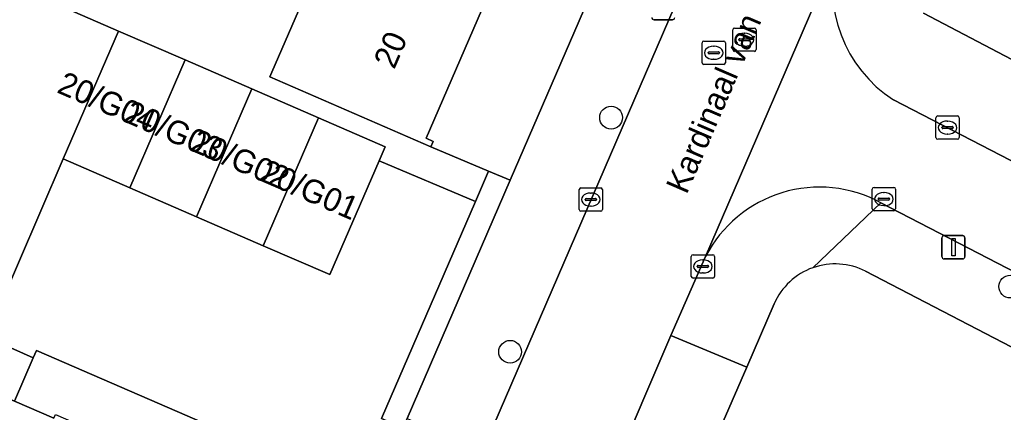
# Model space of a CAD drawing. Extents: x 162803 to 163818, y 381639 to 382475.
# Drawn here: x 163434.73 to 163477.02, y 381838.38 to 381855.24 of the extents above; entities that cross this region are included whole.
import ezdxf

# ---------------------------------------------------------------- set-up
doc = ezdxf.new("R2010")
doc.units = 0
for name, color, linetype in [('IMGEO_Boom', 7, 'Continuous'), ('IMGEO_Erf', 7, 'Continuous'), ('IMGEO_Groenvoorziening', 7, 'Continuous'), ('IMGEO_Kolk', 7, 'Continuous'), ('IMGEO_Lichtmast', 7, 'Continuous'), ('IMGEO_Openbare_ruimte_label', 7, 'Continuous'), ('IMGEO_Pand', 7, 'Continuous'), ('IMGEO_Pand_nummerreeks', 7, 'Continuous'), ('IMGEO_Rijbaan_lokaal_open', 7, 'Continuous'), ('IMGEO_Rioolput', 7, 'Continuous'), ('IMGEO_Voetpad_open', 7, 'Continuous')]:
    doc.layers.add(name, color=color, linetype=linetype)

msp = doc.modelspace()

# ---------------------------------------------------------------- linework, layer by layer
at = {"layer": 'IMGEO_Boom'}
for centre in [(163460.155, 381851.033), (163477.316, 381843.779), (163455.815, 381840.978)]:
    msp.add_circle(centre, 0.489, dxfattribs=at)
at = {"layer": 'IMGEO_Erf'}
msp.add_lwpolyline([(163479.77, 381903.625), (163476.457, 381905.086), (163476.35, 381904.843), (163476.029, 381904.985), (163473.779, 381899.806), (163471.381, 381894.284), (163468.981, 381888.761), (163466.582, 381883.238), (163464.183, 381877.716), (163461.785, 381872.194), (163459.386, 381866.672), (163456.986, 381861.148), (163454.588, 381855.626), (163452.208, 381850.148), (163452.502, 381850.014), (163452.411, 381849.78), (163454.888, 381848.734), (163455.817, 381848.343)], close=True, dxfattribs=at)
for points in [[(163436.121, 381855.995), (163438.987, 381854.752), (163441.852, 381853.51), (163444.718, 381852.268), (163447.584, 381851.025), (163450.449, 381849.783), (163450.186, 381849.176), (163454.325, 381847.435), (163454.888, 381848.734), (163452.411, 381849.78), (163445.485, 381852.783), (163445.572, 381852.984), (163447.962, 381858.498)], [(163436.198, 381838.123), (163434.517, 381838.854), (163432.723, 381839.632), (163429.378, 381841.081), (163428.109, 381838.155), (163425.245, 381839.398), (163425.173, 381839.429), (163422.236, 381840.702), (163423.504, 381843.626), (163420.299, 381845.015), (163413.989, 381847.548), (163416.807, 381846.326), (163415.568, 381843.47), (163412.751, 381844.692), (163412.199, 381843.419), (163405.84, 381846.176), (163407.63, 381850.305), (163403.019, 381852.311), (163395.819, 381835.705), (163436.629, 381811.45)], [(163510.339, 381824.751), (163500, 381829.751), (163491.148, 381834.032), (163483.419, 381838.041), (163481.822, 381835.232), (163479.327, 381836.591), (163480.949, 381839.322), (163479.944, 381839.844), (163471.095, 381844.434)], [(163467.165, 381843.034), (163465.988, 381840.322), (163463.432, 381834.438), (163455.158, 381815.381), (163452.711, 381809.747), (163451.053, 381805.927)]]:
    msp.add_lwpolyline(points, dxfattribs=at)
for centre, radius, start, end in [((163469.783, 381841.899), 2.853, 109.5935, 156.5574), ((163469.784, 381841.895), 2.857, 62.6909, 109.5938)]:
    msp.add_arc(centre, radius, start, end, dxfattribs=at)
at = {"layer": 'IMGEO_Groenvoorziening'}
msp.add_lwpolyline([(163473.59, 381855.524), (163481.149, 381851.558), (163490.613, 381873.486)], dxfattribs=at)
for points in [[(163455.817, 381848.343), (163454.888, 381848.734), (163454.325, 381847.435), (163450.286, 381838.112), (163451.209, 381837.708), (163451.387, 381838.119)], [(163435.32, 381840.713), (163434.517, 381838.854), (163436.198, 381838.123), (163436.268, 381838.286), (163439.015, 381837.095), (163441.782, 381835.896), (163441.712, 381835.735), (163448.992, 381832.592), (163449.775, 381834.399), (163449.934, 381834.765), (163435.46, 381841.037)]]:
    msp.add_lwpolyline(points, close=True, dxfattribs=at)
at = {"layer": 'IMGEO_Kolk'}
for p, q in [((163474.195, 381851.103), (163475.047, 381851.103)), ((163474.12, 381850.177), (163474.12, 381851.029)), ((163474.608, 381850.883), (163474.633, 381850.883)), ((163475.121, 381851.029), (163475.121, 381850.177)), ((163474.379, 381850.597), (163474.379, 381850.609)), ((163474.817, 381850.56), (163474.419, 381850.56)), ((163474.422, 381850.646), (163474.82, 381850.646)), ((163474.631, 381850.323), (163474.606, 381850.323)), ((163474.863, 381850.609), (163474.863, 381850.597)), ((163475.047, 381850.103), (163474.195, 381850.103)), ((163458.783, 381847.089), (163458.783, 381847.941)), ((163458.858, 381848.015), (163459.71, 381848.015)), ((163459.271, 381847.795), (163459.296, 381847.795)), ((163459.784, 381847.941), (163459.784, 381847.089)), ((163471.382, 381847.11), (163471.382, 381847.962)), ((163471.457, 381848.036), (163472.309, 381848.036)), ((163471.87, 381847.816), (163471.895, 381847.816)), ((163472.383, 381847.962), (163472.383, 381847.11)), ((163459.042, 381847.509), (163459.042, 381847.521)), ((163459.48, 381847.472), (163459.082, 381847.472)), ((163459.085, 381847.558), (163459.483, 381847.558)), ((163459.526, 381847.521), (163459.526, 381847.509)), ((163471.641, 381847.53), (163471.641, 381847.542)), ((163472.079, 381847.493), (163471.681, 381847.493)), ((163471.684, 381847.579), (163472.082, 381847.579)), ((163472.125, 381847.542), (163472.125, 381847.53)), ((163459.71, 381847.015), (163458.858, 381847.015)), ((163459.294, 381847.235), (163459.269, 381847.235)), ((163472.309, 381847.036), (163471.457, 381847.036)), ((163471.893, 381847.256), (163471.868, 381847.256)), ((163463.603, 381844.217), (163463.603, 381845.069)), ((163463.678, 381845.143), (163464.53, 381845.143)), ((163464.091, 381844.923), (163464.116, 381844.923)), ((163464.604, 381845.069), (163464.604, 381844.217)), ((163463.862, 381844.637), (163463.862, 381844.649)), ((163464.3, 381844.6), (163463.902, 381844.6)), ((163463.905, 381844.686), (163464.303, 381844.686)), ((163464.114, 381844.363), (163464.089, 381844.363)), ((163464.346, 381844.649), (163464.346, 381844.637)), ((163464.53, 381844.143), (163463.678, 381844.143))]:
    msp.add_line(p, q, dxfattribs=at)
for points in [[(163474.195, 381851.103), (163475.047, 381851.103)], [(163474.12, 381850.177), (163474.12, 381851.029)], [(163475.121, 381851.029), (163475.121, 381850.177)], [(163475.047, 381850.103), (163474.195, 381850.103)], [(163458.783, 381847.089), (163458.783, 381847.941)], [(163458.858, 381848.015), (163459.71, 381848.015)], [(163459.784, 381847.941), (163459.784, 381847.089)], [(163471.382, 381847.11), (163471.382, 381847.962)], [(163471.457, 381848.036), (163472.309, 381848.036)], [(163472.383, 381847.962), (163472.383, 381847.11)], [(163459.71, 381847.015), (163458.858, 381847.015)], [(163472.309, 381847.036), (163471.457, 381847.036)], [(163463.603, 381844.217), (163463.603, 381845.069)], [(163463.678, 381845.143), (163464.53, 381845.143)], [(163464.604, 381845.069), (163464.604, 381844.217)], [(163464.53, 381844.143), (163463.678, 381844.143)]]:
    msp.add_lwpolyline(points, dxfattribs=at)
for centre, radius, start, end in [((163474.197, 381851.027), 0.0765, 91.552, 178.448), ((163474.197, 381851.027), 0.0765, 91.552, 178.448), ((163475.045, 381851.027), 0.0765, 1.552, 88.448), ((163475.045, 381851.027), 0.0765, 1.552, 88.448), ((163474.419, 381850.606), 0.0403, 85.8775, 175.7526), ((163474.416, 381850.596), 0.0366, 178.938, 274.7102), ((163474.82, 381850.603), 0.043, 264.8664, 352.4533), ((163474.824, 381850.608), 0.0386, 1.7309, 96.639), ((163474.197, 381850.179), 0.0765, 181.552, 268.448), ((163474.197, 381850.179), 0.0765, 181.552, 268.448), ((163475.045, 381850.179), 0.0765, 271.552, 358.448), ((163475.045, 381850.179), 0.0765, 271.552, 358.448), ((163458.86, 381847.939), 0.0765, 91.552, 178.448), ((163458.86, 381847.939), 0.0765, 91.552, 178.448), ((163459.708, 381847.939), 0.0765, 1.552, 88.448), ((163459.708, 381847.939), 0.0765, 1.552, 88.448), ((163471.459, 381847.96), 0.0765, 91.552, 178.448), ((163471.459, 381847.96), 0.0765, 91.552, 178.448), ((163472.307, 381847.96), 0.0765, 1.552, 88.448), ((163472.307, 381847.96), 0.0765, 1.552, 88.448), ((163459.082, 381847.518), 0.0403, 85.8775, 175.7526), ((163459.079, 381847.508), 0.0366, 178.938, 274.7102), ((163459.483, 381847.515), 0.043, 264.8664, 352.4533), ((163459.487, 381847.52), 0.0386, 1.7309, 96.639), ((163471.681, 381847.539), 0.0403, 85.8775, 175.7526), ((163471.678, 381847.529), 0.0366, 178.938, 274.7102), ((163472.082, 381847.536), 0.043, 264.8664, 352.4533), ((163472.086, 381847.541), 0.0386, 1.7309, 96.639), ((163458.86, 381847.091), 0.0765, 181.552, 268.448), ((163458.86, 381847.091), 0.0765, 181.552, 268.448), ((163459.708, 381847.091), 0.0765, 271.552, 358.448), ((163459.708, 381847.091), 0.0765, 271.552, 358.448), ((163471.459, 381847.112), 0.0765, 181.552, 268.448), ((163471.459, 381847.112), 0.0765, 181.552, 268.448), ((163472.307, 381847.112), 0.0765, 271.552, 358.448), ((163472.307, 381847.112), 0.0765, 271.552, 358.448), ((163463.68, 381845.067), 0.0765, 91.552, 178.448), ((163463.68, 381845.067), 0.0765, 91.552, 178.448), ((163464.528, 381845.067), 0.0765, 1.552, 88.448), ((163464.528, 381845.067), 0.0765, 1.552, 88.448), ((163463.902, 381844.646), 0.0403, 85.8775, 175.7526), ((163463.899, 381844.636), 0.0366, 178.938, 274.7102), ((163464.303, 381844.643), 0.043, 264.8664, 352.4533), ((163464.307, 381844.648), 0.0386, 1.7309, 96.639), ((163463.68, 381844.219), 0.0765, 181.552, 268.448), ((163463.68, 381844.219), 0.0765, 181.552, 268.448), ((163464.528, 381844.219), 0.0765, 271.552, 358.448), ((163464.528, 381844.219), 0.0765, 271.552, 358.448)]:
    msp.add_arc(centre, radius, start, end, dxfattribs=at)
for centre, major_axis, ratio, start_param, end_param in [((163474.607, 381850.603), (-0.387, 0.002), 0.722429, 4.712389, 7.853982), ((163474.632, 381850.603), (-0.39, 0.002), 0.717154, 1.570796, 4.712389), ((163459.27, 381847.515), (-0.387, 0.002), 0.722429, 4.712389, 7.853982), ((163459.295, 381847.515), (-0.39, 0.002), 0.717154, 1.570796, 4.712389), ((163471.869, 381847.536), (-0.387, 0.002), 0.722429, 4.712389, 7.853982), ((163471.894, 381847.536), (-0.39, 0.002), 0.717154, 1.570796, 4.712389), ((163464.09, 381844.643), (-0.387, 0.002), 0.722429, 4.712389, 7.853982), ((163464.115, 381844.643), (-0.39, 0.002), 0.717154, 1.570796, 4.712389)]:
    msp.add_ellipse(centre, major_axis=major_axis, ratio=ratio, start_param=start_param, end_param=end_param, dxfattribs=at)
at = {"layer": 'IMGEO_Lichtmast'}
for p, q in [((163462.792, 381855.237), (163462.002, 381855.237)), ((163462.002, 381855.237), (163462.792, 381855.237)), ((163474.378, 381845.067), (163474.378, 381845.867)), ((163474.378, 381845.867), (163474.378, 381845.067)), ((163474.478, 381845.967), (163475.268, 381845.967)), ((163475.268, 381845.967), (163474.478, 381845.967)), ((163475.368, 381845.867), (163475.368, 381845.067)), ((163475.368, 381845.067), (163475.368, 381845.867)), ((163475.268, 381844.967), (163474.478, 381844.967)), ((163474.478, 381844.967), (163475.268, 381844.967))]:
    msp.add_line(p, q, dxfattribs=at)
msp.add_lwpolyline([(163474.798, 381845.842), (163474.948, 381845.842), (163474.948, 381845.092), (163474.798, 381845.092), (163474.798, 381845.842)], dxfattribs=at)
for centre, start, end in [((163462.002, 381855.337), 180, 270), ((163462.002, 381855.337), 180, 270), ((163462.792, 381855.337), 270, 0), ((163462.792, 381855.337), 270, 0), ((163474.478, 381845.867), 90, 180), ((163474.478, 381845.867), 90, 180), ((163475.268, 381845.867), 0, 90), ((163475.268, 381845.867), 360, 90), ((163474.478, 381845.067), 180, 270), ((163474.478, 381845.067), 180, 270), ((163475.268, 381845.067), 270, 0), ((163475.268, 381845.067), 270, 0)]:
    msp.add_arc(centre, 0.1, start, end, dxfattribs=at)
at = {"layer": 'IMGEO_Pand'}
for points in [[(163447.962, 381858.498), (163445.572, 381852.984), (163445.485, 381852.783), (163452.411, 381849.78), (163452.502, 381850.014), (163452.208, 381850.148), (163454.588, 381855.626)], [(163438.987, 381854.752), (163436.121, 381855.995), (163433.255, 381857.237), (163430.874, 381851.744), (163427.569, 381844.119), (163432.128, 381842.14), (163433.704, 381842.563), (163436.605, 381849.259)], [(163436.605, 381849.259), (163439.471, 381848.017), (163441.852, 381853.51), (163438.987, 381854.752)], [(163441.852, 381853.51), (163439.471, 381848.017), (163442.337, 381846.775), (163444.718, 381852.268)], [(163447.584, 381851.025), (163444.718, 381852.268), (163442.337, 381846.775), (163445.202, 381845.532)], [(163450.186, 381849.176), (163450.449, 381849.783), (163447.584, 381851.025), (163445.202, 381845.532), (163448.068, 381844.29)]]:
    msp.add_lwpolyline(points, close=True, dxfattribs=at)
at = {"layer": 'IMGEO_Rijbaan_lokaal_open'}
for points in [[(163462.723, 381841.684), (163464.217, 381845.074), (163469.867, 381858.162), (163476.868, 381874.378), (163471.893, 381876.637), (163454.618, 381836.679), (163453.03, 381833.006), (163452.976, 381832.881), (163452.381, 381831.536), (163450.868, 381828.115), (163445.164, 381814.911), (163443.559, 381811.462), (163442.774, 381809.67), (163447.896, 381807.44), (163448.811, 381809.6), (163449.421, 381811.034), (163451.945, 381816.796), (163460.206, 381835.802)], [(163454.325, 381847.435), (163450.186, 381849.176), (163448.068, 381844.29), (163445.202, 381845.532), (163442.337, 381846.775), (163439.471, 381848.017), (163436.605, 381849.259), (163433.704, 381842.563), (163432.128, 381842.14), (163435.32, 381840.713), (163435.46, 381841.037), (163449.934, 381834.765), (163451.209, 381837.708), (163450.286, 381838.112)]]:
    msp.add_lwpolyline(points, close=True, dxfattribs=at)
for points in [[(163469.867, 381858.162), (163464.217, 381845.074)], [(163500, 381837.571), (163486.838, 381844.283), (163483.505, 381846.007), (163482.763, 381846.391), (163472.291, 381851.795)], [(163471.754, 381847.37), (163487.24, 381839.376), (163500, 381833.05), (163510.521, 381828.057), (163516.325, 381825.302), (163533.779, 381817.249), (163554.293, 381808.419), (163561.102, 381805.535), (163577.998, 381798.72), (163599.538, 381790.571), (163605.983, 381788.269), (163626.738, 381781.138), (163633.654, 381778.796), (163637.107, 381777.697), (163639.414, 381776.915)]]:
    msp.add_lwpolyline(points, dxfattribs=at)
for centre, radius, start, end in [((163475.436, 381856.637), 5.774, 164.6873, 236.9977), ((163469.107, 381842.54), 5.508, 61.2793, 152.6054)]:
    msp.add_arc(centre, radius, start, end, dxfattribs=at)
at = {"layer": 'IMGEO_Rioolput'}
for p, q in [((163465.387, 381853.953), (163465.387, 381854.805)), ((163465.462, 381854.879), (163466.314, 381854.879)), ((163465.875, 381854.659), (163465.9, 381854.659)), ((163466.388, 381854.805), (163466.388, 381853.953)), ((163464.068, 381853.39), (163464.068, 381854.242)), ((163464.143, 381854.316), (163464.995, 381854.316)), ((163464.556, 381854.096), (163464.581, 381854.096)), ((163465.069, 381854.242), (163465.069, 381853.39)), ((163465.646, 381854.373), (163465.646, 381854.385)), ((163466.084, 381854.336), (163465.686, 381854.336)), ((163465.689, 381854.422), (163466.087, 381854.422)), ((163465.898, 381854.099), (163465.873, 381854.099)), ((163466.13, 381854.385), (163466.13, 381854.373)), ((163464.327, 381853.81), (163464.327, 381853.822)), ((163464.765, 381853.773), (163464.367, 381853.773)), ((163464.37, 381853.859), (163464.768, 381853.859)), ((163464.811, 381853.822), (163464.811, 381853.81)), ((163466.314, 381853.879), (163465.462, 381853.879)), ((163464.995, 381853.316), (163464.143, 381853.316)), ((163464.579, 381853.536), (163464.554, 381853.536))]:
    msp.add_line(p, q, dxfattribs=at)
for points in [[(163465.387, 381853.953), (163465.387, 381854.805)], [(163465.462, 381854.879), (163466.314, 381854.879)], [(163466.388, 381854.805), (163466.388, 381853.953)], [(163464.068, 381853.39), (163464.068, 381854.242)], [(163464.143, 381854.316), (163464.995, 381854.316)], [(163465.069, 381854.242), (163465.069, 381853.39)], [(163466.314, 381853.879), (163465.462, 381853.879)], [(163464.995, 381853.316), (163464.143, 381853.316)]]:
    msp.add_lwpolyline(points, dxfattribs=at)
for centre, radius, start, end in [((163465.464, 381854.803), 0.0765, 91.552, 178.448), ((163465.464, 381854.803), 0.0765, 91.552, 178.448), ((163466.312, 381854.803), 0.0765, 1.552, 88.448), ((163466.312, 381854.803), 0.0765, 1.552, 88.448), ((163464.145, 381854.24), 0.0765, 91.552, 178.448), ((163464.145, 381854.24), 0.0765, 91.552, 178.448), ((163464.993, 381854.24), 0.0765, 1.552, 88.448), ((163464.993, 381854.24), 0.0765, 1.552, 88.448), ((163465.686, 381854.382), 0.0403, 85.8775, 175.7526), ((163465.683, 381854.372), 0.0366, 178.938, 274.7102), ((163466.087, 381854.379), 0.043, 264.8664, 352.4533), ((163466.091, 381854.384), 0.0386, 1.7309, 96.639), ((163464.367, 381853.819), 0.0403, 85.8775, 175.7526), ((163464.364, 381853.809), 0.0366, 178.938, 274.7102), ((163464.768, 381853.816), 0.043, 264.8664, 352.4533), ((163464.772, 381853.821), 0.0386, 1.7309, 96.639), ((163465.464, 381853.955), 0.0765, 181.552, 268.448), ((163465.464, 381853.955), 0.0765, 181.552, 268.448), ((163466.312, 381853.955), 0.0765, 271.552, 358.448), ((163466.312, 381853.955), 0.0765, 271.552, 358.448), ((163464.145, 381853.392), 0.0765, 181.552, 268.448), ((163464.145, 381853.392), 0.0765, 181.552, 268.448), ((163464.993, 381853.392), 0.0765, 271.552, 358.448), ((163464.993, 381853.392), 0.0765, 271.552, 358.448)]:
    msp.add_arc(centre, radius, start, end, dxfattribs=at)
for centre, major_axis, ratio, start_param, end_param in [((163465.874, 381854.379), (-0.387, 0.002), 0.722429, 4.712389, 7.853982), ((163465.899, 381854.379), (-0.39, 0.002), 0.717154, 1.570796, 4.712389), ((163464.555, 381853.816), (-0.387, 0.002), 0.722429, 4.712389, 7.853982), ((163464.58, 381853.816), (-0.39, 0.002), 0.717154, 1.570796, 4.712389)]:
    msp.add_ellipse(centre, major_axis=major_axis, ratio=ratio, start_param=start_param, end_param=end_param, dxfattribs=at)
at = {"layer": 'IMGEO_Voetpad_open'}
for points in [[(163486.887, 381920.052), (163484.202, 381913.856), (163480.407, 381905.096), (163479.77, 381903.625), (163455.817, 381848.343), (163451.387, 381838.119), (163454.618, 381836.679), (163471.893, 381876.637)], [(163431.903, 381857.968), (163429.555, 381852.549), (163426.001, 381844.348), (163422.756, 381845.755), (163421.091, 381846.477), (163403.547, 381853.528), (163403.019, 381852.311), (163407.63, 381850.305), (163413.989, 381847.548), (163420.299, 381845.015), (163423.504, 381843.626), (163423.554, 381843.742), (163426.491, 381842.468), (163429.427, 381841.195), (163429.378, 381841.081), (163432.723, 381839.632), (163434.517, 381838.854), (163435.32, 381840.713), (163432.128, 381842.14), (163427.569, 381844.119), (163430.874, 381851.744), (163433.255, 381857.237)], [(163472.291, 381851.795), (163482.763, 381846.391), (163484.337, 381850.044), (163481.149, 381851.558), (163473.59, 381855.524)], [(163510.075, 381827.117), (163510.521, 381828.057), (163500, 381833.05), (163487.24, 381839.376), (163471.754, 381847.37), (163468.826, 381844.587)], [(163468.826, 381844.587), (163471.754, 381847.37)], [(163464.217, 381845.074), (163462.723, 381841.684), (163465.988, 381840.322), (163467.165, 381843.034)], [(163471.095, 381844.434), (163479.944, 381839.844), (163480.949, 381839.322), (163479.327, 381836.591), (163481.822, 381835.232), (163483.419, 381838.041), (163491.148, 381834.032), (163500, 381829.751), (163510.339, 381824.751), (163514.191, 381822.919), (163535.946, 381813.079), (163554.407, 381804.897), (163558.59, 381803.327), (163559.941, 381802.767), (163573.895, 381797.053), (163581.187, 381794.234), (163580.279, 381791.819), (163583.345, 381790.766), (163584.228, 381793.059), (163589.771, 381790.916), (163599.635, 381787.326), (163603.532, 381785.876), (163617.902, 381780.975), (163637.177, 381774.637)]]:
    msp.add_lwpolyline(points, dxfattribs=at)
msp.add_lwpolyline([(163465.988, 381840.322), (163462.723, 381841.684), (163460.206, 381835.802), (163463.432, 381834.438)], close=True, dxfattribs=at)
for centre, radius, start, end in [((163475.436, 381856.637), 5.774, 164.6873, 236.9977), ((163469.107, 381842.54), 5.508, 61.2793, 152.6054), ((163469.783, 381841.899), 2.853, 109.5935, 156.5574), ((163469.784, 381841.895), 2.857, 62.6909, 109.5938)]:
    msp.add_arc(centre, radius, start, end, dxfattribs=at)

# ---------------------------------------------------------------- texts
at = {"layer": 'IMGEO_Openbare_ruimte_label'}
msp.add_text('Kardinaal van Rossumlaan', height=1, rotation=66.666, dxfattribs=at).set_placement((163463.401, 381847.701))
at = {"layer": 'IMGEO_Pand_nummerreeks'}
for s, rotation, p in [('20', 66.562, (163450.833, 381853.071)), ('20/G04', 336.5611, (163436.288, 381852.13)), ('20/G03', 336.5611, (163439.154, 381850.887)), ('20/G02', 336.5611, (163442.015, 381849.647)), ('20/G01', 336.5603, (163444.989, 381848.357))]:
    msp.add_text(s, height=1, rotation=rotation, dxfattribs=at).set_placement(p)

doc.saveas('drawing.dxf')
